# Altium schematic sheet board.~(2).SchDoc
size A3
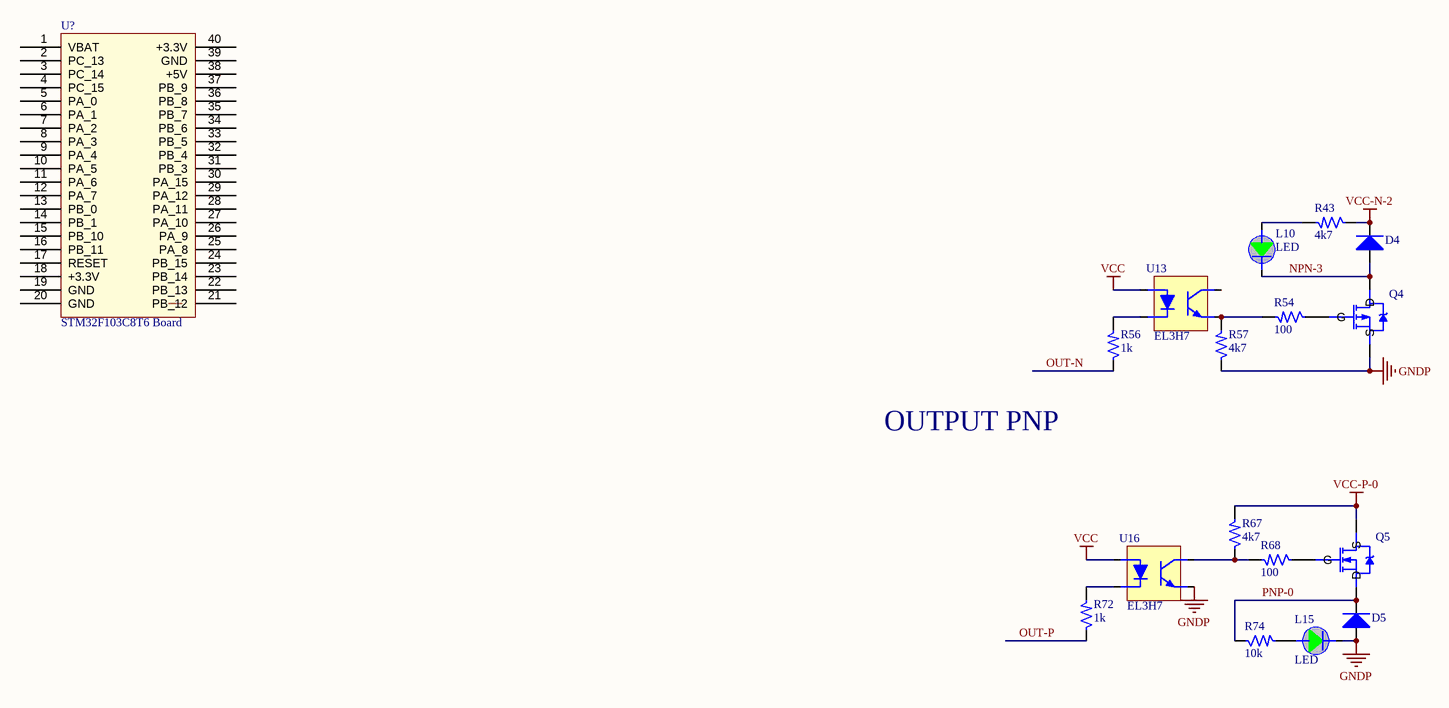
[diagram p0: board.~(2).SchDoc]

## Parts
D4  (no value)  [DIODE SS24 SMA]
D5  (no value)  [DIODE SS24 SMA]
L10  LED  [LED GREEN 0603 SMD]
L15  LED  [LED GREEN 0603 SMD]
Q4  MOSFET N  [AO3401 Mosfet P SOT23]  (value not drawn)
Q5  MOSFET P  [AO3401 Mosfet P SOT23]  (value not drawn)
R43  4k7  [RES 0603]
R54  100  [RES 0603]
R56  1k  [RES 0603]
R57  4k7  [RES 0603]
R67  4k7  [RES 0603]
R68  100  [RES 0603]
R72  1k  [RES 0603]
R74  10k  [RES 0603]
U13  EL3H7  [SSOP4]
U16  EL3H7  [SSOP4]
U?  STM32F103C8T6 Board  [STM32 Blue Pill]

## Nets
GNDP: D5.1(A) L15.2(Katot) Q4.2(S) R57.1 U16.3
VCC: U13.1 U16.1
VCC-N-2: D4.2(K) R43.1
VCC-P-0: Q5.1(S) R67.2
NPN-3: D4.1(A) L10.2(Katot) Q4.1(D)
OUT-N: R56.1
OUT-P: R72.1
PNP-0: D5.2(K) Q5.2(D) R74.1
NetL10_1: L10.1(anot) R43.2
NetL15_1: L15.1(anot) R74.2
NetQ4_3: Q4.3(G) R54.1
NetQ5_3: Q5.3(G) R68.1
NetR54_2: R54.2 R57.2 U13.3
NetR56_2: R56.2 U13.2
NetR67_1: R67.1 R68.2 U16.4
NetR72_2: R72.2 U16.2

Not connected (* = marked no-connect by the designer): U13 4; U? 1(VBAT) 2(PC_13) 3(PC_14) 4(PC_15) 5(PA_0) 6(PA_1) 7(PA_2) 8(PA_3) 9(PA_4) 10(PA_5) 11(PA_6) 12(PA_7) 13(PB_0) 14(PB_1) 15(PB_10) 16(PB_11) 17(RESET) 18(+3.3V) 19(GND) 20(GND) 21(PB_12) 22(PB_13) 23(PB_14) 24(PB_15) 25(PA_8) 26(PA_9) 27(PA_10) 28(PA_11) 29(PA_12) 30(PA_15) 31(PB_3) 32(PB_4) 33(PB_5) 34(PB_6) 35(PB_7) 36(PB_8) 37(PB_9) 38(+5V) 39(GND) 40(+3.3V)

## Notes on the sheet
- OUTPUT PNP

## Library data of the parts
D4 D5 = diode SMA
L10 L15 = LED GREEN SMD
Q4 = MOSFET N AO3402
Q5 = MOSFET P AO3401
R43 R54 R56 R57 R67 R68 R72 R74 = res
